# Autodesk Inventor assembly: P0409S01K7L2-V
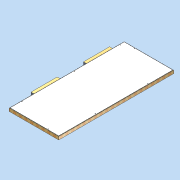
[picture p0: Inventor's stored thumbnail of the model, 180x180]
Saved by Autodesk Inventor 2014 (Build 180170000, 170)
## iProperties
Created: 2011-04
Part Number: P0409S01K7L2-V
Document SubType Name: Assembly
Designer: david.appleford
Description: 1w x 2.25w  01 Panel - 7 Locks 2 Lugs
Mass: 47000 g
Surface Area: 71309.8 cm^2
Volume: 251414 cm^3
Density: 0.186943 g/cm^3
Cost Center: £155.00
Justset: False
Title: 1w x 2.25w  01 Panel - 7 Locks 2 Lugs
Author: david.appleford
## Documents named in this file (3)
- C:\Documents and Settings\john.everitt\Local Settings\My Documents\Vault\Production MkII\VIRTUAL ELEMENTS\Virtual Walls\Virtual Timber + MgO\P0409S01K7L2-V.iam
- C:\Documents and Settings\john.everitt\Local Settings\My Documents\Vault\Production MkII\VIRTUAL ELEMENTS\Virtual Lugs\Superceded Lugs\LA02M3V.ipt
- C:\Documents and Settings\john.everitt\Local Settings\My Documents\Vault\Production MkII\Virtual Elements\Virtual Walls\Virtual Timber + MgO\P0409S01K7-V.ipt
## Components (3 placed, 2 different names)
1. P0409S01K7-V:1 — Mate:5, Mate:6, Flush:9, Flush:10
2. LA02M3V:5 — Mate:6, Flush:9, Mate:12
3. LA02M3V:2 — Mate:5, Flush:10, Mate:12
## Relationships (5: Mate 3, Flush 2)
- Mate:5: P0409S01K7-V:1 ↔ LA02M3V:2
- Mate:6: P0409S01K7-V:1 ↔ LA02M3V:5
- Flush:9: P0409S01K7-V:1 ↔ LA02M3V:5
- Flush:10: P0409S01K7-V:1 ↔ LA02M3V:2
- Mate:12: LA02M3V:5 ↔ LA02M3V:2
## Named parameters: t = 1 mm, Cl = 2 mm
